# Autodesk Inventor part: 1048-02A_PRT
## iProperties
Created: 2007-03
Part Number: 1048-02A_PRT
Document SubType Name: Modeling
Designer: Andy Moles
Material: Steel
Mass: 39.2963 g
Surface Area: 36.8314 cm^2
Volume: 5.00589 cm^3
Density: 7.85 g/cm^3
Author: Andy Moles
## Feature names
1. Base1
